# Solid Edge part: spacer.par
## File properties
Author: Binay
Template: sync ansi part.par
Last saved by: CADCIM
Revision: 16
Application: Solid Edge
Accuracy: 0.990
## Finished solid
Body 1: solid body, 4 faces, 4 edges, 0 vertices.
  Faces by surface: cylinder 2, plane 2
  Edges by curve: circle 4
Bounding box of the edges (mm): 31.750 x 31.750 x 34.925, from (-23.8946, 129.8949, -17.4625) to (7.8554, 161.6449, 17.4625).
Cylindrical faces by radius (mm): R12.7 x1, R15.875 x1
Planar faces by outward normal: +z 1, -z 1
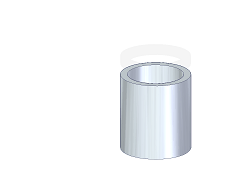
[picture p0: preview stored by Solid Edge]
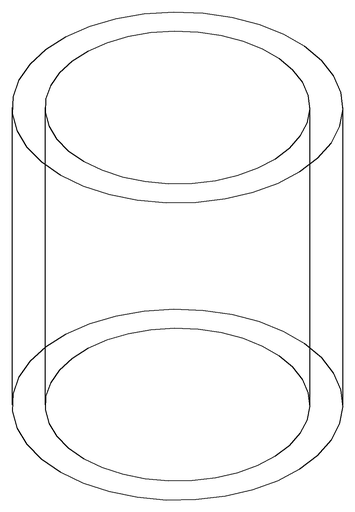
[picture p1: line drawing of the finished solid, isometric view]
